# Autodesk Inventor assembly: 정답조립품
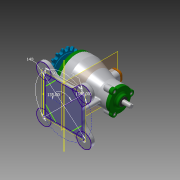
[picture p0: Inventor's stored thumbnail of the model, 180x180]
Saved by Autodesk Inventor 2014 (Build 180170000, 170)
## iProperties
Created: 2018-03
Part Number: 정답조립품
Document SubType Name: Assembly
Designer: kb542
Author: kb542
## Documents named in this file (15)
- C:\Users\kb542\Desktop\480307V1024\정답조립품.iam
- C:\Users\kb542\Desktop\480307V1024\본체.ipt
- C:\Users\kb542\Desktop\480307V1024\뒤커버.ipt
- C:\Users\kb542\Desktop\480307V1024\마개.ipt
- C:\Users\kb542\Desktop\480307V1024\베어링-6200.ipt
- C:\Users\kb542\Desktop\480307V1024\베어링-6203.ipt
- C:\Users\kb542\Desktop\480307V1024\볼트 M4 x 12.ipt
- 볼트 M4 x 12.ipt
- C:\Users\kb542\Desktop\480307V1024\스프로킷.ipt
- C:\Users\kb542\Desktop\480307V1024\앞커버.ipt
- C:\Users\kb542\Desktop\480307V1024\오일 실 10 20 7.ipt
- C:\Users\kb542\Desktop\480307V1024\오일 실 17 30 8.ipt
- C:\Users\kb542\Desktop\480307V1024\축.ipt
- C:\Users\kb542\Desktop\480307V1024\키 5 x 5.ipt
- 키 5 x 5.ipt
